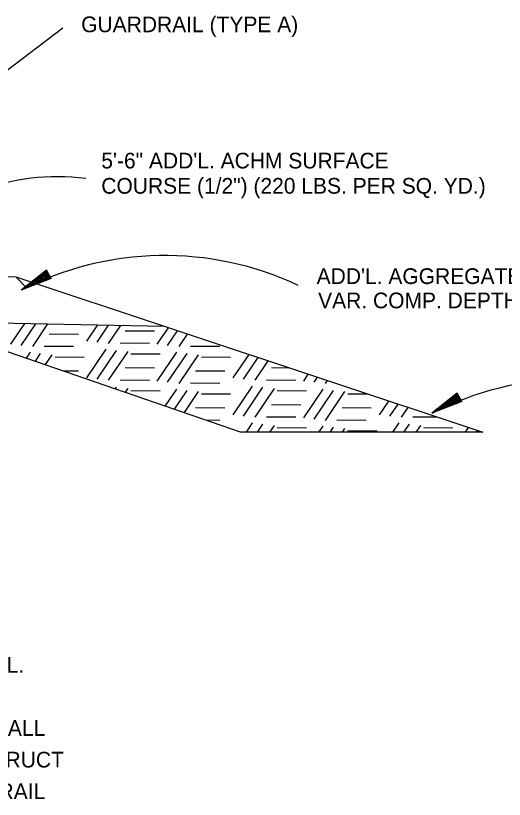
# Model space of a CAD drawing. Extents: x 1929624 to 1935547, y 596315 to 605721.
# Drawn here: x 1933162.8 to 1933351.8, y 604598.3 to 604901.3 of the extents above; entities that cross this region are included whole.
import ezdxf

# ---------------------------------------------------------------- set-up
doc = ezdxf.new("R2010")
doc.units = 0
doc.layers.add('Default', color=7, linetype='Continuous')
doc.layers.add('R_Border', color=7, linetype='Continuous')

msp = doc.modelspace()

# ---------------------------------------------------------------- linework, layer by layer
at = {"layer": 'Default'}
for p, q in [((1933111.72, 604844.22), (1933181.03, 604896.61)), ((1933028.14, 604805.69), (1933162.8, 604800.31)), ((1933174.66, 604802.94), (1933164.92, 604795.16)), ((1933174.83, 604802.64), (1933166.71, 604796.17)), ((1933174.98, 604802.37), (1933168.53, 604797.26)), ((1933175.13, 604802.13), (1933170.3, 604798.29)), ((1933176.53, 604799.72), (1933174.66, 604802.94)), ((1933162.8, 604800.31), (1933343.43, 604740.26)), ((1933162.8, 604800.31), (1933167.03, 604796.1)), ((1933176.53, 604799.72), (1933164.92, 604795.16)), ((1933176.36, 604799.99), (1933166.71, 604796.17)), ((1933176.19, 604800.26), (1933168.53, 604797.26)), ((1933176.04, 604800.5), (1933170.3, 604798.29)), ((1933175.27, 604801.83), (1933172.1, 604799.32)), ((1933175.89, 604800.77), (1933172.1, 604799.32)), ((1933175.45, 604801.56), (1933173.92, 604800.36)), ((1933175.74, 604801.07), (1933173.92, 604800.36)), ((1932826.87, 604789.04), (1933220.25, 604781.21)), ((1933125.91, 604783.09), (1933249.97, 604740.26)), ((1933333.55, 604755.34), (1933323.81, 604747.57)), ((1933333.72, 604755.05), (1933325.6, 604748.58)), ((1933333.87, 604754.78), (1933327.42, 604749.66)), ((1933334.02, 604754.53), (1933329.2, 604750.69)), ((1933334.17, 604754.24), (1933330.99, 604751.73)), ((1933334.34, 604753.97), (1933332.81, 604752.76)), ((1933334.63, 604753.47), (1933332.81, 604752.76)), ((1933335.42, 604752.12), (1933333.55, 604755.34)), ((1933335.42, 604752.12), (1933323.81, 604747.57)), ((1933335.25, 604752.39), (1933325.6, 604748.58)), ((1933335.08, 604752.66), (1933327.42, 604749.66)), ((1933334.93, 604752.91), (1933329.2, 604750.69)), ((1933334.78, 604753.18), (1933330.99, 604751.73)), ((1933343.43, 604740.26), (1933249.97, 604740.26)), ((1933342.9, 604740.26), (1933343.03, 604740.39)), ((1933343.33, 604740.29), (1933343.36, 604740.26))]:
    msp.add_line(p, q, dxfattribs=at)
for centre in [(1933220.43, 604686.83), (1933379.32, 604639.24)]:
    msp.add_arc(centre, 121.72, 64.8876, 117.1378, dxfattribs=at)
msp.add_ellipse((1933185.01, 604798.43), major_axis=(-60.8, 7.42), ratio=0.655798, start_param=4.712389, end_param=6.093533, dxfattribs=at)
at = {"layer": 'R_Border'}
for p, q in [((1933160.95, 604774.3), (1933166.34, 604782.29)), ((1933164.93, 604773.84), (1933170.58, 604782.2)), ((1933169.38, 604773.37), (1933175.28, 604782.11)), ((1933190.31, 604775.51), (1933194.51, 604781.73)), ((1933194.3, 604775.04), (1933198.75, 604781.64)), ((1933198.75, 604774.58), (1933203.45, 604781.55)), ((1933175.78, 604778.29), (1933187.09, 604778.2)), ((1933205.15, 604779.5), (1933216.46, 604779.4)), ((1933217.57, 604774.3), (1933221.87, 604780.67)), ((1933221.55, 604773.84), (1933225.38, 604779.5)), ((1933226, 604773.37), (1933229.27, 604778.21)), ((1933203.2, 604774.77), (1933214.51, 604774.67)), ((1933173.83, 604773.56), (1933185.14, 604773.47)), ((1933190.31, 604761.25), (1933197.82, 604772.37)), ((1933194.3, 604760.78), (1933201.81, 604771.91)), ((1933230.45, 604773.56), (1933241.76, 604773.47)), ((1933166.94, 604768.92), (1933168.46, 604771.17)), ((1933170.43, 604767.72), (1933172.44, 604770.7)), ((1933174.29, 604766.39), (1933176.89, 604770.24)), ((1933178, 604769.41), (1933189.31, 604769.31)), ((1933198.75, 604760.32), (1933206.26, 604771.45)), ((1933207.37, 604770.61), (1933218.68, 604770.52)), ((1933217.57, 604760.04), (1933225.08, 604771.17)), ((1933221.55, 604759.58), (1933229.06, 604770.7)), ((1933226, 604759.11), (1933233.51, 604770.24)), ((1933234.63, 604769.41), (1933245.93, 604769.31)), ((1933246.93, 604761.25), (1933253.05, 604770.31)), ((1933250.92, 604760.78), (1933256.56, 604769.14)), ((1933255.37, 604760.32), (1933260.45, 604767.85)), ((1933181.26, 604763.98), (1933187.09, 604763.94)), ((1933205.15, 604765.23), (1933216.46, 604765.14)), ((1933232.4, 604764.03), (1933243.71, 604763.94)), ((1933261.77, 604765.23), (1933268.47, 604765.18)), ((1933274.19, 604760.04), (1933275.97, 604762.68)), ((1933203.2, 604760.5), (1933214.51, 604760.41)), ((1933259.82, 604760.5), (1933271.13, 604760.41)), ((1933278.18, 604759.58), (1933279.49, 604761.52)), ((1933282.62, 604759.11), (1933283.38, 604760.22)), ((1933201.39, 604757.03), (1933201.81, 604757.65)), ((1933205.26, 604755.7), (1933206.26, 604757.18)), ((1933220.67, 604750.38), (1933225.08, 604756.91)), ((1933230.45, 604759.3), (1933241.76, 604759.21)), ((1933246.93, 604746.98), (1933254.44, 604758.11)), ((1933250.92, 604746.52), (1933258.43, 604757.65)), ((1933255.37, 604746.06), (1933262.88, 604757.18)), ((1933274.19, 604745.78), (1933281.7, 604756.91)), ((1933207.37, 604756.35), (1933218.68, 604756.26)), ((1933224.16, 604749.17), (1933229.06, 604756.44)), ((1933228.02, 604747.84), (1933233.51, 604755.98)), ((1933234.63, 604755.14), (1933245.93, 604755.05)), ((1933263.99, 604756.35), (1933275.3, 604756.26)), ((1933278.18, 604745.31), (1933285.68, 604756.44)), ((1933282.62, 604744.85), (1933290.13, 604755.98)), ((1933291.25, 604755.14), (1933298.84, 604755.08)), ((1933261.77, 604750.97), (1933273.08, 604750.88)), ((1933303.56, 604746.98), (1933307.16, 604752.32)), ((1933307.54, 604746.52), (1933310.67, 604751.15)), ((1933232.4, 604749.77), (1933243.71, 604749.67)), ((1933289.02, 604749.77), (1933300.33, 604749.67)), ((1933311.99, 604746.06), (1933314.56, 604749.86)), ((1933236.28, 604744.99), (1933241.76, 604744.94)), ((1933259.82, 604746.24), (1933271.13, 604746.15)), ((1933287.07, 604745.04), (1933298.38, 604744.94)), ((1933316.44, 604746.24), (1933325.66, 604746.17)), ((1933252.02, 604740.26), (1933254.44, 604743.85)), ((1933256.32, 604740.26), (1933258.43, 604743.39)), ((1933261.08, 604740.26), (1933262.88, 604742.92)), ((1933263.99, 604742.09), (1933275.3, 604742)), ((1933280.09, 604740.26), (1933281.7, 604742.64)), ((1933284.39, 604740.26), (1933285.68, 604742.18)), ((1933289.15, 604740.26), (1933290.13, 604741.72)), ((1933308.64, 604740.26), (1933311.06, 604743.85)), ((1933312.94, 604740.26), (1933315.05, 604743.39)), ((1933317.7, 604740.26), (1933319.5, 604742.92)), ((1933320.61, 604742.09), (1933331.92, 604742)), ((1933336.71, 604740.26), (1933337.94, 604742.08)), ((1933291.25, 604740.88), (1933302.56, 604740.79)), ((1933341.01, 604740.26), (1933341.45, 604740.92))]:
    msp.add_line(p, q, dxfattribs=at)

# ---------------------------------------------------------------- texts
at = {"layer": 'Default'}
for s, p in [('GUARDRAIL (TYPE A)', (1933188.12, 604894.91)), ('5\'-6" ADD\'L. ACHM SURFACE ', (1933195.9, 604842.24)), ('COURSE (1/2") (220 LBS. PER SQ. YD.)', (1933195.9, 604832.48)), ("ADD'L. AGGREGATE BASE COURSE (CLASS 7)", (1933279.2, 604797.56)), ('VAR. COMP. DEPTH (VAR. TONS/STA.)', (1933279.77, 604788.17)), ('   1.  REFER TO STD. DWG. GR-9 FOR SLOPE REQUIREMENTS BEHIND GUARDRAIL.', (1932838.84, 604647.31)), ('   2.  FOR HORIZONTAL AND VERTICAL CONTROL, THE GUARDRAIL WIDENING SHALL', (1932838.84, 604622.86)), ('       MATCH THE SLOPES AND GRADES OF THE MAIN LANE SHOULDERS.  CONSTRUCT', (1932838.84, 604610.63)), ('       BRIDGE APPROACH AND MAIN LANE TRANSITIONS BEFORE PAVING GUARDRAIL', (1932838.84, 604598.41))]:
    msp.add_text(s, height=6.075, rotation=360, dxfattribs=at).set_placement(p)

doc.saveas('drawing.dxf')
